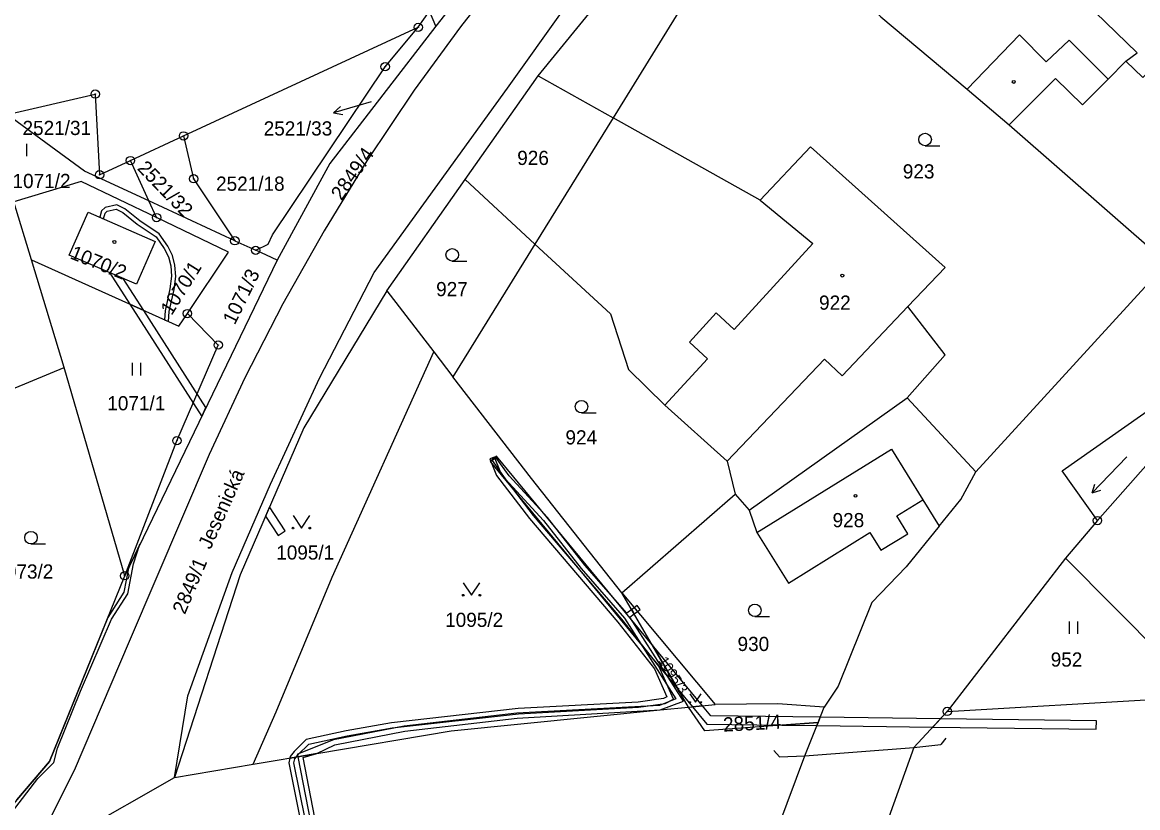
# Model space of a CAD drawing. Extents: x -562167 to -556918, y -1077891 to -1070763.
# Drawn here: x -559234.3 to -559100.6, y -1074697.3 to -1074603.1 of the extents above; entities that cross this region are included whole.
import ezdxf

# ---------------------------------------------------------------- set-up
doc = ezdxf.new("R2010")
doc.units = 0
for name, color, linetype in [('Hranice parcel', 7, 'Continuous'), ('Parcelní čísla', 7, 'Continuous'), ('Pop  PČ popisy', 7, 'Continuous'), ('Vnitřní kresba', 7, 'Continuous'), ('Věcná břemena k části', 7, 'Continuous'), ('Značky bodu BP', 7, 'Continuous'), ('Značky budov', 7, 'Continuous'), ('Značky kultur', 7, 'Continuous')]:
    doc.layers.add(name, color=color, linetype=linetype)

msp = doc.modelspace()

# ---------------------------------------------------------------- linework, layer by layer
at = {"layer": 'Hranice parcel'}
for p, q in [((-559172.51, -1074609.53), (-559150.91, -1074583.08)), ((-559146.66, -1074587.3), (-559163.52, -1074614.57)), ((-559182.25, -1074600.34), (-559184.75, -1074603.58)), ((-559186.87, -1074603.73), (-559185.54, -1074601.81)), ((-559184.75, -1074603.58), (-559185.54, -1074601.81)), ((-559215, -1074616.74), (-559186.87, -1074603.73)), ((-559181.27, -1074621.98), (-559172.51, -1074609.53)), ((-559172.51, -1074609.53), (-559163.52, -1074614.57)), ((-559163.52, -1074614.57), (-559172.88, -1074629.71)), ((-559116.05, -1074615.4), (-559097.13, -1074631.95)), ((-559221.38, -1074619.7), (-559215, -1074616.74)), ((-559219.16, -1074624.54), (-559221.38, -1074619.7)), ((-559190.66, -1074635.33), (-559181.27, -1074621.98)), ((-559181.27, -1074621.98), (-559172.88, -1074629.71)), ((-559233.22, -1074631.62), (-559235.35, -1074624.66)), ((-559218.24, -1074626.54), (-559219.16, -1074624.54)), ((-559208.86, -1074629.31), (-559219.16, -1074624.54)), ((-559208.86, -1074629.31), (-559206.36, -1074630.46)), ((-559172.88, -1074629.71), (-559182.71, -1074645.62)), ((-559203.8, -1074631.65), (-559206.36, -1074630.46)), ((-559229.3, -1074644.5), (-559233.22, -1074631.62)), ((-559203.8, -1074631.65), (-559222.06, -1074669.47)), ((-559120.05, -1074657.03), (-559097.13, -1074631.95)), ((-559190.66, -1074635.33), (-559185.02, -1074642.63)), ((-559185.02, -1074642.63), (-559182.71, -1074645.62)), ((-559246.95, -1074651.83), (-559229.3, -1074644.5)), ((-559222.06, -1074669.47), (-559229.3, -1074644.5)), ((-559147.22, -1074661.59), (-559128.25, -1074648.13)), ((-559128.25, -1074648.13), (-559120.05, -1074657.03)), ((-559162.47, -1074671.51), (-559148.87, -1074659.68)), ((-559148.87, -1074659.68), (-559147.22, -1074661.59)), ((-559105.46, -1074662.86), (-559109.29, -1074667.38)), ((-559109.29, -1074667.38), (-559123.47, -1074685.73)), ((-559109.29, -1074667.38), (-559092.87, -1074683.92)), ((-559162.47, -1074671.51), (-559151.29, -1074684.9)), ((-559154.49, -1074685.22), (-559162.47, -1074671.51)), ((-559123.47, -1074685.73), (-559092.87, -1074683.92)), ((-559154.49, -1074685.22), (-559151.29, -1074684.9)), ((-559138.94, -1074687.05), (-559138.22, -1074685.23)), ((-559123.47, -1074685.73), (-559127.45, -1074690.06)), ((-559140.55, -1074691.07), (-559138.94, -1074687.05)), ((-559143.65, -1074699.39), (-559140.55, -1074691.07)), ((-559127.45, -1074690.06), (-559130.46, -1074698.39)), ((-559216.08, -1074693.66), (-559206.68, -1074692.07)), ((-559234.57, -1074704.15), (-559216.08, -1074693.66))]:
    msp.add_line(p, q, dxfattribs=at)
for points in [[(-559148.84, -1074568.33), (-559153.15, -1074571.45), (-559157.45, -1074575.18), (-559162.93, -1074580.49), (-559167.98, -1074586.26), (-559174.83, -1074594.73), (-559181.81, -1074603.66), (-559187.37, -1074611.26), (-559193.04, -1074619.74), (-559198.16, -1074628.13), (-559203.1, -1074636.86), (-559207.67, -1074645.75), (-559211.93, -1074654.95), (-559221.53, -1074677.33), (-559228.12, -1074692.82), (-559231.29, -1074699.08), (-559233.33, -1074702.52), (-559234.57, -1074704.15)], [(-559216.08, -1074693.66), (-559214.49, -1074683.88), (-559209.19, -1074669.07), (-559204.57, -1074658.49), (-559198.72, -1074645.77), (-559192.15, -1074633.1), (-559176.17, -1074611.04), (-559162.62, -1074592.02), (-559155.82, -1074584.06), (-559148.79, -1074578.52), (-559141.38, -1074574.85), (-559134.73, -1074573.16), (-559126.24, -1074573.66), (-559119.99, -1074574.66)], [(-559116.05, -1074615.4), (-559110.49, -1074609.88), (-559107.27, -1074613.01), (-559104.17, -1074609.93), (-559102.04, -1074607.79), (-559100, -1074609.75), (-559094.2, -1074603.85), (-559096.13, -1074601.95), (-559090.54, -1074596.03), (-559094.38, -1074592.3), (-559098.51, -1074588.29)], [(-559137.14, -1074596.79), (-559134.88, -1074598.95), (-559131.41, -1074602.49), (-559121.08, -1074611.16), (-559116.05, -1074615.4)], [(-559206.36, -1074630.46), (-559204.87, -1074629.71), (-559204.34, -1074628.59), (-559190.84, -1074608.45), (-559186.87, -1074603.73)], [(-559184.75, -1074603.58), (-559197.49, -1074620.07), (-559203.8, -1074631.65)], [(-559236.15, -1074614.18), (-559225.6, -1074611.74), (-559225.08, -1074621.41), (-559221.38, -1074619.7)], [(-559219.16, -1074624.54), (-559226.89, -1074620.96), (-559236.15, -1074614.18)], [(-559128.25, -1074648.13), (-559123.72, -1074642.97), (-559128.17, -1074637.2), (-559123.71, -1074632.53), (-559139.86, -1074618.04), (-559145.88, -1074624.45), (-559163.52, -1074614.57)], [(-559215, -1074616.74), (-559213.8, -1074621.89), (-559208.86, -1074629.31)], [(-559218.24, -1074626.54), (-559227.29, -1074622.22), (-559235.35, -1074624.66)], [(-559220.64, -1074634.52), (-559228.71, -1074631.05), (-559226.44, -1074625.87), (-559218.4, -1074629.4), (-559220.64, -1074634.52)], [(-559214.55, -1074638.04), (-559209.6, -1074630.67), (-559218.24, -1074626.54)], [(-559105.46, -1074662.86), (-559109.7, -1074656.9), (-559066.49, -1074626.58)], [(-559066.49, -1074626.58), (-559089.67, -1074644.99), (-559105.46, -1074662.86)], [(-559172.88, -1074629.71), (-559163.82, -1074638.07), (-559161.67, -1074644.75), (-559157.3, -1074649.04), (-559149.85, -1074655.75), (-559148.87, -1074659.68)], [(-559233.22, -1074631.62), (-559215.58, -1074639.56), (-559214.55, -1074638.04)], [(-559190.66, -1074635.33), (-559200.59, -1074651.74), (-559208.22, -1074669.37), (-559216.08, -1074693.66)], [(-559222.06, -1074669.47), (-559215.8, -1074653.28), (-559210.85, -1074641.81), (-559214.55, -1074638.04)], [(-559206.68, -1074692.07), (-559203.91, -1074685.76), (-559197.19, -1074669.62), (-559185.02, -1074642.63)], [(-559162.47, -1074671.51), (-559173.28, -1074657.83), (-559182.71, -1074645.62)], [(-559124.42, -1074663.51), (-559121.85, -1074660.32), (-559120.05, -1074657.03)], [(-559147.22, -1074661.59), (-559146.29, -1074664.29), (-559142.48, -1074670.34), (-559132.73, -1074664.29), (-559131.41, -1074666.42), (-559128.2, -1074664.43), (-559129.52, -1074662.3), (-559126.38, -1074660.35), (-559124.42, -1074663.51)], [(-559124.42, -1074663.51), (-559128.38, -1074668.41), (-559132.49, -1074672.66), (-559136.54, -1074682.69), (-559138.22, -1074685.23)], [(-559234.98, -1074696.34), (-559231.08, -1074691.72), (-559222.06, -1074669.47)], [(-559206.68, -1074692.07), (-559199.03, -1074690.78), (-559182.91, -1074688.05), (-559157.87, -1074685.56), (-559154.49, -1074685.22)], [(-559138.94, -1074687.05), (-559152.52, -1074688.06), (-559154.49, -1074685.22)], [(-559138.22, -1074685.23), (-559143.76, -1074684.84), (-559151.29, -1074684.9)]]:
    msp.add_lwpolyline(points, dxfattribs=at)
at = {"layer": 'Pop  PČ popisy'}
for p, q in [((-559194.15, -1074613.14), (-559197.04, -1074613.97)), ((-559197.04, -1074613.97), (-559196.21, -1074613.21)), ((-559192.5, -1074612.68), (-559194.15, -1074613.14)), ((-559197.04, -1074613.97), (-559195.93, -1074614.17))]:
    msp.add_line(p, q, dxfattribs=at)
at = {"layer": 'Vnitřní kresba'}
for p, q in [((-559105.74, -1074601.9), (-559100.71, -1074606.79)), ((-559121.08, -1074611.16), (-559114.81, -1074604.65)), ((-559114.81, -1074604.65), (-559111.59, -1074607.88)), ((-559111.59, -1074607.88), (-559108.85, -1074605.27)), ((-559108.85, -1074605.27), (-559104.17, -1074609.93)), ((-559102.04, -1074607.79), (-559100.71, -1074606.79)), ((-559145.88, -1074624.45), (-559139.57, -1074629.63)), ((-559148.99, -1074639.94), (-559139.57, -1074629.63)), ((-559136.07, -1074645.5), (-559128.17, -1074637.2)), ((-559154.37, -1074641.47), (-559151.16, -1074637.96)), ((-559151.16, -1074637.96), (-559148.99, -1074639.94)), ((-559154.37, -1074641.47), (-559152.2, -1074643.45)), ((-559157.3, -1074649.04), (-559152.2, -1074643.45)), ((-559149.85, -1074655.75), (-559138.17, -1074643.49)), ((-559138.17, -1074643.49), (-559136.07, -1074645.5)), ((-559146.29, -1074664.29), (-559130.15, -1074654.28)), ((-559130.15, -1074654.28), (-559126.38, -1074660.35)), ((-559127.45, -1074690.06), (-559124.24, -1074689.71)), ((-559123.62, -1074688.92), (-559124.24, -1074689.71)), ((-559144.26, -1074690.43), (-559143.59, -1074691.17)), ((-559143.59, -1074691.17), (-559140.55, -1074691.07)), ((-559140.55, -1074691.07), (-559127.45, -1074690.06))]:
    msp.add_line(p, q, dxfattribs=at)
at = {"layer": 'Věcná břemena k části'}
for points in [[(-559220.56, -1074627.33), (-559218.31, -1074628.86), (-559217.33, -1074630.24), (-559216.8, -1074631.25), (-559216.54, -1074632.33), (-559216.45, -1074633.56), (-559216.65, -1074635.07), (-559217.23, -1074637.7), (-559217.3, -1074638.79), (-559216.82, -1074639), (-559216.73, -1074637.78), (-559216.15, -1074635.15), (-559215.95, -1074633.58), (-559216.04, -1074632.25), (-559216.32, -1074631.07), (-559216.91, -1074629.98), (-559217.95, -1074628.5), (-559220.26, -1074626.93), (-559222.04, -1074625.49), (-559223.02, -1074625.02), (-559224.39, -1074625.32), (-559224.85, -1074625.72), (-559225.06, -1074626.48), (-559224.59, -1074626.68), (-559224.41, -1074626), (-559224.15, -1074625.78), (-559223.08, -1074625.54), (-559222.3, -1074625.91)], [(-559223.89, -1074633.12), (-559221.45, -1074636.92), (-559219.78, -1074637.67), (-559222.25, -1074633.83)], [(-559212.83, -1074650.36), (-559212.32, -1074649.3), (-559219.78, -1074637.67), (-559221.45, -1074636.92)], [(-559178.25, -1074655.76), (-559155.72, -1074683.1), (-559158.84, -1074677.75), (-559177.48, -1074655.13)], [(-559202.26, -1074691.32), (-559201.51, -1074691.2), (-559201.29, -1074690.92), (-559199.99, -1074689.64), (-559195.39, -1074688.65), (-559189.99, -1074687.68), (-559174.84, -1074686), (-559160.46, -1074685.23), (-559157.29, -1074684.77), (-559156.29, -1074684.28), (-559158.05, -1074680.29), (-559162.49, -1074674.67), (-559173.07, -1074662.24), (-559176.99, -1074657.14), (-559177.74, -1074655.24), (-559178.3, -1074655.46), (-559177.51, -1074657.44), (-559173.53, -1074662.62), (-559162.95, -1074675.05), (-559158.57, -1074680.61), (-559157.07, -1074684), (-559157.47, -1074684.19), (-559160.52, -1074684.63), (-559174.88, -1074685.4), (-559190.07, -1074687.08), (-559195.51, -1074688.07), (-559200.29, -1074689.08), (-559201.75, -1074690.52), (-559202.22, -1074691.14)], [(-559176.46, -1074657.86), (-559171.85, -1074662.85), (-559167.35, -1074668.59), (-559162.15, -1074674.54), (-559155.99, -1074684.22), (-559157.97, -1074685.02), (-559175.06, -1074685.95), (-559188.58, -1074687.51), (-559197.03, -1074689.14), (-559201.36, -1074690.87), (-559201.3, -1074691.16), (-559199.03, -1074690.78), (-559196.86, -1074689.72), (-559188.49, -1074688.1), (-559175.01, -1074686.55), (-559157.87, -1074685.56), (-559155.09, -1074684.51), (-559161.51, -1074674.44), (-559160.99, -1074674.05), (-559161.29, -1074673.53), (-559161.87, -1074673.96), (-559166.89, -1074668.21), (-559171.39, -1074662.47), (-559175.99, -1074657.49), (-559177.52, -1074655.32), (-559178.01, -1074655.67)], [(-559203.68, -1074664.63), (-559202.84, -1074664.09), (-559204.69, -1074661.21), (-559205.17, -1074662.31)], [(-559221.61, -1074668.54), (-559222.15, -1074671.44), (-559224.09, -1074674.49), (-559231.08, -1074691.72), (-559234.98, -1074696.34), (-559236.11, -1074697.67), (-559238.72, -1074701.06), (-559241.55, -1074706.48), (-559241.1, -1074706.71), (-559238.3, -1074701.34), (-559232.46, -1074693.77), (-559230.56, -1074691.86), (-559230.12, -1074690.13), (-559227.35, -1074683.3), (-559223.63, -1074674.69), (-559221.67, -1074671.62), (-559221.01, -1074668.03), (-559220.23, -1074665.69)], [(-559160.59, -1074673.76), (-559160.98, -1074673.3), (-559161.29, -1074673.53), (-559160.99, -1074674.05)], [(-559160.98, -1074673.3), (-559160.59, -1074673.76), (-559160.27, -1074673.53), (-559160.63, -1074673.04)], [(-559152.82, -1074685.05), (-559158.84, -1074677.75), (-559155.72, -1074683.1), (-559154.02, -1074685.17)], [(-559154.02, -1074685.17), (-559152.3, -1074687.26), (-559143.28, -1074687.37), (-559138.94, -1074687.05), (-559138.7, -1074686.43), (-559151.82, -1074686.26), (-559152.82, -1074685.05)], [(-559143.28, -1074687.37), (-559139.09, -1074687.43), (-559138.94, -1074687.05)], [(-559139.09, -1074687.43), (-559125.19, -1074687.6), (-559124.28, -1074686.62), (-559138.7, -1074686.43), (-559138.94, -1074687.05)], [(-559124.28, -1074686.62), (-559125.19, -1074687.6), (-559105.6, -1074687.86), (-559105.58, -1074686.86)], [(-559201.51, -1074691.2), (-559202.26, -1074691.32), (-559202.39, -1074691.89), (-559199.62, -1074705.68), (-559199.24, -1074706.71), (-559199.67, -1074707.68), (-559200.46, -1074708.16), (-559202.36, -1074708.46), (-559208.2, -1074710.64), (-559199.81, -1074708.47), (-559199.19, -1074708.1), (-559198.6, -1074706.73), (-559199.04, -1074705.52), (-559201.77, -1074691.89), (-559201.66, -1074691.4)], [(-559197.73, -1074707.94), (-559197.13, -1074707.78), (-559197.68, -1074706.77), (-559200.68, -1074691.24), (-559199.03, -1074690.78), (-559201.3, -1074691.16), (-559198.25, -1074706.97)]]:
    msp.add_lwpolyline(points, close=True, dxfattribs=at)
at = {"layer": 'Značky bodu BP'}
for centre, radius in [((-559186.87, -1074603.73), 0.5), ((-559186.87, -1074603.73), 0.0303), ((-559190.84, -1074608.45), 0.5), ((-559190.84, -1074608.45), 0.0303), ((-559225.6, -1074611.74), 0.5), ((-559225.6, -1074611.74), 0.0303), ((-559215, -1074616.74), 0.5), ((-559215, -1074616.74), 0.0303), ((-559221.38, -1074619.7), 0.5), ((-559221.38, -1074619.7), 0.0303), ((-559225.08, -1074621.41), 0.5), ((-559225.08, -1074621.41), 0.0303), ((-559213.8, -1074621.89), 0.5), ((-559213.8, -1074621.89), 0.0303), ((-559218.24, -1074626.54), 0.5), ((-559218.24, -1074626.54), 0.0303), ((-559208.86, -1074629.31), 0.5), ((-559208.86, -1074629.31), 0.0303), ((-559206.36, -1074630.46), 0.5), ((-559206.36, -1074630.46), 0.0303), ((-559214.55, -1074638.04), 0.5), ((-559214.55, -1074638.04), 0.0303), ((-559210.85, -1074641.81), 0.5), ((-559210.85, -1074641.81), 0.0303), ((-559215.8, -1074653.28), 0.5), ((-559215.8, -1074653.28), 0.0303), ((-559105.46, -1074662.86), 0.5), ((-559105.46, -1074662.86), 0.0303), ((-559222.06, -1074669.47), 0.5), ((-559222.06, -1074669.47), 0.0303), ((-559123.47, -1074685.73), 0.5), ((-559123.47, -1074685.73), 0.0303)]:
    msp.add_circle(centre, radius, dxfattribs=at)
at = {"layer": 'Značky budov'}
for centre in [(-559115.49, -1074610.27), (-559223.29, -1074629.46), (-559136.04, -1074633.49), (-559134.46, -1074659.89)]:
    msp.add_circle(centre, 0.175, dxfattribs=at)
at = {"layer": 'Značky kultur'}
for p, q in [((-559233.79, -1074619.18), (-559233.79, -1074617.68)), ((-559126.12, -1074617.92), (-559124.37, -1074617.92)), ((-559182.8, -1074631.75), (-559181.05, -1074631.75)), ((-559221.11, -1074645.45), (-559221.11, -1074643.95)), ((-559220.11, -1074645.45), (-559220.11, -1074643.95)), ((-559167.31, -1074649.95), (-559165.56, -1074649.95)), ((-559101.94, -1074655.23), (-559106.11, -1074659.54)), ((-559106.11, -1074659.54), (-559105.79, -1074658.49)), ((-559106.11, -1074659.54), (-559105.07, -1074659.19)), ((-559233.3, -1074665.65), (-559231.55, -1074665.65)), ((-559146.53, -1074674.36), (-559144.78, -1074674.36)), ((-559108.81, -1074676.45), (-559108.81, -1074674.95)), ((-559107.81, -1074676.45), (-559107.81, -1074674.95))]:
    msp.add_line(p, q, dxfattribs=at)
for points in [[(-559201.88, -1074662.26), (-559200.88, -1074663.76), (-559199.88, -1074662.26)], [(-559181.49, -1074670.3), (-559180.49, -1074671.8), (-559179.49, -1074670.3)], [(-559154.3, -1074683.62), (-559153.63, -1074684.63), (-559152.96, -1074683.62)]]:
    msp.add_lwpolyline(points, dxfattribs=at)
for centre, radius in [((-559126.12, -1074617.17), 0.75), ((-559182.8, -1074631), 0.75), ((-559167.31, -1074649.2), 0.75), ((-559233.3, -1074664.9), 0.75), ((-559201.88, -1074663.76), 0.1), ((-559199.88, -1074663.76), 0.1), ((-559181.49, -1074671.8), 0.1), ((-559179.49, -1074671.8), 0.1), ((-559146.53, -1074673.61), 0.75), ((-559154.3, -1074684.63), 0.067), ((-559152.96, -1074684.63), 0.067)]:
    msp.add_circle(centre, radius, dxfattribs=at)

# ---------------------------------------------------------------- texts
at = {"layer": 'Parcelní čísla'}
for s, p in [('2521/31', (-559234.31, -1074616.64)), ('2521/33', (-559205.4, -1074616.7)), ('926', (-559175.01, -1074620.23)), ('923', (-559128.79, -1074621.85)), ('1071/2', (-559235.51, -1074623)), ('2521/18', (-559211.11, -1074623.32)), ('927', (-559184.73, -1074635.96)), ('922', (-559138.83, -1074637.58)), ('1071/1', (-559224.15, -1074649.64)), ('924', (-559169.23, -1074653.73)), ('928', (-559137.21, -1074663.65)), ('1095/1', (-559203.9, -1074667.53)), ('1073/2', (-559237.57, -1074669.81)), ('1095/2', (-559183.65, -1074675.6)), ('930', (-559148.6, -1074678.49)), ('952', (-559111.06, -1074680.36))]:
    msp.add_text(s, height=1.7, dxfattribs=at).set_placement(p)
for s, height, rotation, p in [('2849/4', 1.7, 55, (-559196.08, -1074624.59)), ('2521/32', 1.7, 314, (-559220.65, -1074620.71)), ('1070/2', 1.7, 338, (-559228.72, -1074631.4)), ('1070/1', 1.7, 58, (-559216.44, -1074638.35)), ('1071/3', 1.7, 64, (-559208.87, -1074639.49)), ('2849/1', 1.7, 67, (-559214.85, -1074674.19)), ('1095/3', 1.19, 303, (-559158.11, -1074679.65)), ('2851/4', 1.7, 3, (-559150.29, -1074688.16))]:
    msp.add_text(s, height=height, rotation=rotation, dxfattribs=at).set_placement(p)
at = {"layer": 'Pop  PČ popisy'}
msp.add_text('Jesenická', height=1.7, rotation=66, dxfattribs=at).set_placement((-559211.77, -1074666.4))

doc.saveas('drawing.dxf')
